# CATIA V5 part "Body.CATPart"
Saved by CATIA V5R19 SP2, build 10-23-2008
Part number: Body
Definition: design
Nomenclature: Body
Source: Unknown
Bounding box of the stored display mesh (mm): x -59 to 59, y -37.5 to 34.5, z 0 to 11
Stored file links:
  Z:\fausse table rondelle-20220905T211342Z-001\fausse table rondelle\Body.CATPart
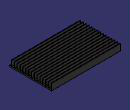
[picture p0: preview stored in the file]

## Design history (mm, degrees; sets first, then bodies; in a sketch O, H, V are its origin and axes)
AxisSystem1: origin (0, 0, 0), X (1, 0, 0), Y (0, 1, 0), Z (0, 0, 1)
Body1 "MANIFOLD_SOLID_BREP #120" (main body)
  Solid1: solid without history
